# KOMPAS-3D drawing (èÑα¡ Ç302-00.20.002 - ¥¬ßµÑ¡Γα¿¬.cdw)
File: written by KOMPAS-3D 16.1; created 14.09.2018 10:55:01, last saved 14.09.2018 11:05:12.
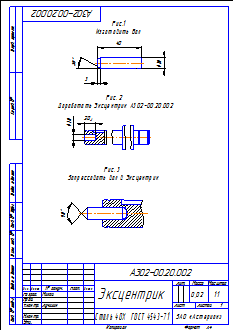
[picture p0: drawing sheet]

Sheet 1: A4, portrait

Title block, sheet 1: name: Эксцентрик; designation: А302-00.20.002; material: Сталь 40Х  ГОСТ 4543-71; mass: 0,02; scale: 1:1; sheets: 1; organisation: ЗАО «Астерион»; sheet format: A4; drawn by: Милов; technical control: Лучихин

Views: Вид 1, Проекционный вид 2, Вид 3, Проекционный вид 4, Вид:3, Вид:4
Referenced files in Z:\Мембранные насосы\Мембранный электропривод\А302-00.00.000 - ASTRA-302 (МЭ200)\3Д\Доработка\: Керн А302-00.20.002 - Эксцентрик.m3d
Referenced files in Z:\Мембранные насосы\Мембранный электропривод\А302-00.00.000 - ASTRA-302 (МЭ200)\3Д\: А302-00.20.002 - Эксцентрик.m3d
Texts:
  Рис. 3
  Запрессовать вал в  Эксцентрик
  Рис.1
  Изготовить Вал
  Рис. 2
  Доработать  Эксцентрик   А302-00.20.002
Dimensions and other numbers on the sheet: 40; 3; 10; 20; 1:1; 1; 0,02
